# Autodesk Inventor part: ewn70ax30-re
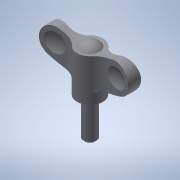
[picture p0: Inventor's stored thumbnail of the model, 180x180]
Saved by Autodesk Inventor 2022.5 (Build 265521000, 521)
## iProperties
Created: 2016-12
Part Number: ewn70ax30-re
Material: 一般
Document SubType Name: Modeling
Designer: imaocorp
Density: 1 g/cm^3
Appearance: 既定
Author: imaocorp
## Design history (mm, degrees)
node "ewn70ax30-re.x_t1"
node "ewn70ax30-re"
node "Base1"
